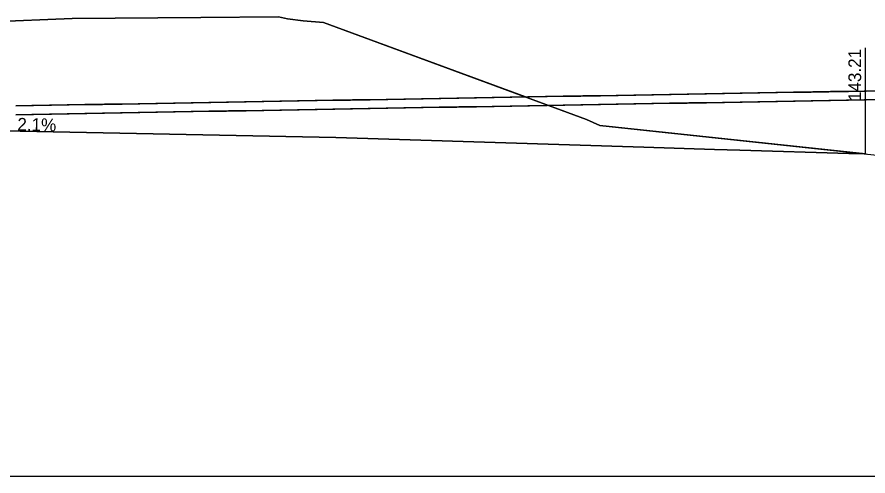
# Model space of a CAD drawing. Extents: x -26 to 4403, y -13 to 9578.
# Drawn here: x 1132.06 to 1180.11, y 1000 to 1025.95 of the extents above; entities that cross this region are included whole.
import ezdxf

# ---------------------------------------------------------------- set-up
doc = ezdxf.new("R2010")
doc.units = 0
for name, color, linetype in [('CONST_LV3', 7, 'Continuous'), ('DTM_CORRIDOR', 7, 'Continuous'), ('DTM_P_FINISHED_GRADE', 7, 'Continuous'), ('DTM_X_GROUND', 7, 'Continuous'), ('SLOPE_STAKES_FILL', 7, 'Continuous'), ('XS_CELL', 7, 'Continuous'), ('XS_M_SHAPES_EARTHWORK', 7, 'Continuous'), ('XS_P_DR_GRAVEL', 7, 'Continuous'), ('XS_P_GROUND', 7, 'Continuous'), ('XS_P_TX_CLEARZONE', 7, 'Continuous'), ('XS_P_TX_FS_BS', 7, 'Continuous')]:
    doc.layers.add(name, color=color, linetype=linetype)

msp = doc.modelspace()

# ---------------------------------------------------------------- linework, layer by layer
at = {"layer": 'CONST_LV3'}
msp.add_lwpolyline([(1132, 1020.927), (1132.897, 1020.942), (1133, 1020.944), (1133.897, 1020.96), (1134, 1020.961), (1134.897, 1020.977), (1135, 1020.979), (1135.897, 1020.995), (1136, 1020.996), (1136.897, 1021.012), (1137, 1021.014), (1137.897, 1021.029), (1138, 1021.031), (1138.897, 1021.047), (1139, 1021.049), (1139.897, 1021.064), (1140, 1021.066), (1140.897, 1021.082), (1141, 1021.083), (1141.897, 1021.099), (1142, 1021.101), (1142.897, 1021.117), (1143, 1021.118), (1143.897, 1021.134), (1144, 1021.136), (1144.897, 1021.151), (1145, 1021.153), (1145.897, 1021.169), (1146, 1021.171), (1146.897, 1021.186), (1147, 1021.188), (1147.897, 1021.204), (1148, 1021.206), (1148.897, 1021.221), (1149, 1021.223), (1149.897, 1021.239), (1150, 1021.24), (1150.897, 1021.256), (1151, 1021.258), (1151.897, 1021.273), (1152, 1021.275), (1152.897, 1021.291), (1153, 1021.293), (1153.897, 1021.308), (1154, 1021.31), (1154.897, 1021.326), (1155, 1021.328), (1155.897, 1021.343), (1156, 1021.345), (1156.897, 1021.361), (1157, 1021.362), (1157.897, 1021.378), (1158, 1021.38), (1158.897, 1021.395), (1159, 1021.397), (1159.897, 1021.413), (1160, 1021.415), (1160.897, 1021.43), (1161, 1021.432), (1161.897, 1021.448), (1162, 1021.45), (1162.897, 1021.465), (1163, 1021.467), (1163.897, 1021.483), (1164, 1021.484), (1164.897, 1021.5), (1165, 1021.502), (1165.897, 1021.518), (1166, 1021.519), (1166.897, 1021.535), (1167, 1021.537), (1167.897, 1021.552), (1168, 1021.554), (1168.897, 1021.57), (1169, 1021.572), (1169.897, 1021.587), (1170, 1021.589), (1170.897, 1021.605), (1171, 1021.606), (1171.897, 1021.622), (1172, 1021.624), (1172.897, 1021.64), (1173, 1021.641), (1173.897, 1021.657), (1174, 1021.659), (1174.897, 1021.674), (1175, 1021.676), (1175.897, 1021.692), (1176, 1021.694), (1176.897, 1021.709), (1177, 1021.711), (1177.897, 1021.727), (1178, 1021.729), (1178.897, 1021.744), (1179, 1021.746), (1179.897, 1021.762), (1180, 1021.763), (1180.897, 1021.779)], dxfattribs=at)
at = {"layer": 'DTM_P_FINISHED_GRADE'}
msp.add_lwpolyline([(1132, 1020.927), (1132.897, 1020.942), (1133, 1020.944), (1133.897, 1020.96), (1134, 1020.961), (1134.897, 1020.977), (1135, 1020.979), (1135.897, 1020.995), (1136, 1020.996), (1136.897, 1021.012), (1137, 1021.014), (1137.897, 1021.029), (1138, 1021.031), (1138.897, 1021.047), (1139, 1021.049), (1139.897, 1021.064), (1140, 1021.066), (1140.897, 1021.082), (1141, 1021.083), (1141.897, 1021.099), (1142, 1021.101), (1142.897, 1021.117), (1143, 1021.118), (1143.897, 1021.134), (1144, 1021.136), (1144.897, 1021.151), (1145, 1021.153), (1145.897, 1021.169), (1146, 1021.171), (1146.897, 1021.186), (1147, 1021.188), (1147.897, 1021.204), (1148, 1021.206), (1148.897, 1021.221), (1149, 1021.223), (1149.897, 1021.239), (1150, 1021.24), (1150.897, 1021.256), (1151, 1021.258), (1151.897, 1021.273), (1152, 1021.275), (1152.897, 1021.291), (1153, 1021.293), (1153.897, 1021.308), (1154, 1021.31), (1154.897, 1021.326), (1155, 1021.328), (1155.897, 1021.343), (1156, 1021.345), (1156.897, 1021.361), (1157, 1021.362), (1157.897, 1021.378), (1158, 1021.38), (1158.897, 1021.395), (1159, 1021.397), (1159.897, 1021.413), (1160, 1021.415), (1160.897, 1021.43), (1161, 1021.432), (1161.897, 1021.448), (1162, 1021.45), (1162.897, 1021.465), (1163, 1021.467), (1163.897, 1021.483), (1164, 1021.484), (1164.897, 1021.5), (1165, 1021.502), (1165.897, 1021.518), (1166, 1021.519), (1166.897, 1021.535), (1167, 1021.537), (1167.897, 1021.552), (1168, 1021.554), (1168.897, 1021.57), (1169, 1021.572), (1169.897, 1021.587), (1170, 1021.589), (1170.897, 1021.605), (1171, 1021.606), (1171.897, 1021.622), (1172, 1021.624), (1172.897, 1021.64), (1173, 1021.641), (1173.897, 1021.657), (1174, 1021.659), (1174.897, 1021.674), (1175, 1021.676), (1175.897, 1021.692), (1176, 1021.694), (1176.897, 1021.709), (1177, 1021.711), (1177.897, 1021.727), (1178, 1021.729), (1178.897, 1021.744), (1179, 1021.746), (1179.897, 1021.762), (1180, 1021.763), (1180.897, 1021.779)], dxfattribs=at)
at = {"layer": 'DTM_X_GROUND'}
msp.add_lwpolyline([(1084.364, 1020.049), (1100.532, 1021.44), (1114.605, 1024.089), (1116.924, 1024.52), (1120.223, 1025.074), (1123.578, 1025.386), (1123.824, 1025.384), (1125.939, 1025.479), (1126.01, 1025.486), (1135.182, 1025.868), (1142.445, 1025.917), (1146.83, 1025.95), (1147.343, 1025.854), (1148.21, 1025.742), (1149.366, 1025.63), (1164.218, 1020.156), (1164.971, 1019.814), (1182.014, 1017.995), (1182.294, 1017.975), (1182.479, 1017.946), (1182.623, 1017.982), (1200.1, 1016.861), (1205.856, 1017.542), (1237.811, 1018.169)], dxfattribs=at)
at = {"layer": 'XS_CELL'}
msp.add_line((1000, 1000), (1250, 1000), dxfattribs=at)
at = {"layer": 'XS_M_SHAPES_EARTHWORK'}
for points in [[(1126.01, 1025.486), (1135.182, 1025.868), (1142.445, 1025.917), (1146.83, 1025.95), (1147.343, 1025.854), (1148.21, 1025.742), (1149.366, 1025.63), (1162.062, 1020.951), (1162, 1020.95), (1161.897, 1020.948), (1161, 1020.932), (1160.897, 1020.93), (1160, 1020.915), (1159.897, 1020.913), (1159, 1020.897), (1158.897, 1020.895), (1158, 1020.88), (1157.897, 1020.878), (1157, 1020.862), (1156.897, 1020.861), (1156, 1020.845), (1155.897, 1020.843), (1155, 1020.828), (1154.897, 1020.826), (1154, 1020.81), (1153.897, 1020.808), (1153, 1020.793), (1152.897, 1020.791), (1152, 1020.775), (1151.897, 1020.773), (1151, 1020.758), (1150.897, 1020.756), (1150, 1020.74), (1149.897, 1020.739), (1149, 1020.723), (1148.897, 1020.721), (1148, 1020.706), (1147.897, 1020.704), (1147, 1020.688), (1146.897, 1020.686), (1146, 1020.671), (1145.897, 1020.669), (1145, 1020.653), (1144.897, 1020.651), (1144, 1020.636), (1143.897, 1020.634), (1143, 1020.618), (1142.897, 1020.617), (1142, 1020.601), (1141.897, 1020.599), (1141, 1020.583), (1140.897, 1020.582), (1140, 1020.566), (1139.897, 1020.564), (1139, 1020.549), (1138.897, 1020.547), (1138, 1020.531), (1137.897, 1020.529), (1137, 1020.514), (1136.897, 1020.512), (1136, 1020.496), (1135.897, 1020.495), (1135, 1020.479), (1134.897, 1020.477), (1134, 1020.461), (1133.897, 1020.46), (1133, 1020.444), (1132.897, 1020.442), (1132, 1020.427)], [(1180.897, 1021.279), (1180, 1021.263), (1179.897, 1021.262), (1179, 1021.246), (1178.897, 1021.244), (1178, 1021.229), (1177.897, 1021.227), (1177, 1021.211), (1176.897, 1021.209), (1176, 1021.194), (1175.897, 1021.192), (1175, 1021.176), (1174.897, 1021.174), (1174, 1021.159), (1173.897, 1021.157), (1173, 1021.141), (1172.897, 1021.14), (1172, 1021.124), (1171.897, 1021.122), (1171, 1021.106), (1170.897, 1021.105), (1170, 1021.089), (1169.897, 1021.087), (1169, 1021.072), (1168.897, 1021.07), (1168, 1021.054), (1167.897, 1021.052), (1167, 1021.037), (1166.897, 1021.035), (1166, 1021.019), (1165.897, 1021.018), (1165, 1021.002), (1164.897, 1021), (1164, 1020.984), (1163.897, 1020.983), (1163, 1020.967), (1162.897, 1020.965), (1162.062, 1020.951), (1164.218, 1020.156), (1164.971, 1019.814), (1182.014, 1017.995)]]:
    msp.add_lwpolyline(points, dxfattribs=at)
at = {"layer": 'XS_P_DR_GRAVEL'}
for points in [[(1180.897, 1021.779), (1180, 1021.763), (1179.897, 1021.762), (1179, 1021.746), (1178.897, 1021.744), (1178, 1021.729), (1177.897, 1021.727), (1177, 1021.711), (1176.897, 1021.709), (1176, 1021.694), (1175.897, 1021.692), (1175, 1021.676), (1174.897, 1021.674), (1174, 1021.659), (1173.897, 1021.657), (1173, 1021.641), (1172.897, 1021.64), (1172, 1021.624), (1171.897, 1021.622), (1171, 1021.606), (1170.897, 1021.605), (1170, 1021.589), (1169.897, 1021.587), (1169, 1021.572), (1168.897, 1021.57), (1168, 1021.554), (1167.897, 1021.552), (1167, 1021.537), (1166.897, 1021.535), (1166, 1021.519), (1165.897, 1021.518), (1165, 1021.502), (1164.897, 1021.5), (1164, 1021.484), (1163.897, 1021.483), (1163, 1021.467), (1162.897, 1021.465), (1162, 1021.45), (1161.897, 1021.448), (1161, 1021.432), (1160.897, 1021.43), (1160, 1021.415), (1159.897, 1021.413), (1159, 1021.397), (1158.897, 1021.395), (1158, 1021.38), (1157.897, 1021.378), (1157, 1021.362), (1156.897, 1021.361), (1156, 1021.345), (1155.897, 1021.343), (1155, 1021.328), (1154.897, 1021.326), (1154, 1021.31), (1153.897, 1021.308), (1153, 1021.293), (1152.897, 1021.291), (1152, 1021.275), (1151.897, 1021.273), (1151, 1021.258), (1150.897, 1021.256), (1150, 1021.24), (1149.897, 1021.239), (1149, 1021.223), (1148.897, 1021.221), (1148, 1021.206), (1147.897, 1021.204), (1147, 1021.188), (1146.897, 1021.186), (1146, 1021.171), (1145.897, 1021.169), (1145, 1021.153), (1144.897, 1021.151), (1144, 1021.136), (1143.897, 1021.134), (1143, 1021.118), (1142.897, 1021.117), (1142, 1021.101), (1141.897, 1021.099), (1141, 1021.083), (1140.897, 1021.082), (1140, 1021.066), (1139.897, 1021.064), (1139, 1021.049), (1138.897, 1021.047), (1138, 1021.031), (1137.897, 1021.029), (1137, 1021.014), (1136.897, 1021.012), (1136, 1020.996), (1135.897, 1020.995), (1135, 1020.979), (1134.897, 1020.977), (1134, 1020.961), (1133.897, 1020.96), (1133, 1020.944), (1132.897, 1020.942), (1132, 1020.927)], [(1132, 1020.427), (1132.897, 1020.442), (1133, 1020.444), (1133.897, 1020.46), (1134, 1020.461), (1134.897, 1020.477), (1135, 1020.479), (1135.897, 1020.495), (1136, 1020.496), (1136.897, 1020.512), (1137, 1020.514), (1137.897, 1020.529), (1138, 1020.531), (1138.897, 1020.547), (1139, 1020.549), (1139.897, 1020.564), (1140, 1020.566), (1140.897, 1020.582), (1141, 1020.583), (1141.897, 1020.599), (1142, 1020.601), (1142.897, 1020.617), (1143, 1020.618), (1143.897, 1020.634), (1144, 1020.636), (1144.897, 1020.651), (1145, 1020.653), (1145.897, 1020.669), (1146, 1020.671), (1146.897, 1020.686), (1147, 1020.688), (1147.897, 1020.704), (1148, 1020.706), (1148.897, 1020.721), (1149, 1020.723), (1149.897, 1020.739), (1150, 1020.74), (1150.897, 1020.756), (1151, 1020.758), (1151.897, 1020.773), (1152, 1020.775), (1152.897, 1020.791), (1153, 1020.793), (1153.897, 1020.808), (1154, 1020.81), (1154.897, 1020.826), (1155, 1020.828), (1155.897, 1020.843), (1156, 1020.845), (1156.897, 1020.861), (1157, 1020.862), (1157.897, 1020.878), (1158, 1020.88), (1158.897, 1020.895), (1159, 1020.897), (1159.897, 1020.913), (1160, 1020.915), (1160.897, 1020.93), (1161, 1020.932), (1161.897, 1020.948), (1162, 1020.95), (1162.897, 1020.965), (1163, 1020.967), (1163.897, 1020.983), (1164, 1020.984), (1164.897, 1021), (1165, 1021.002), (1165.897, 1021.018), (1166, 1021.019), (1166.897, 1021.035), (1167, 1021.037), (1167.897, 1021.052), (1168, 1021.054), (1168.897, 1021.07), (1169, 1021.072), (1169.897, 1021.087), (1170, 1021.089), (1170.897, 1021.105), (1171, 1021.106), (1171.897, 1021.122), (1172, 1021.124), (1172.897, 1021.14), (1173, 1021.141), (1173.897, 1021.157), (1174, 1021.159), (1174.897, 1021.174), (1175, 1021.176), (1175.897, 1021.192), (1176, 1021.194), (1176.897, 1021.209), (1177, 1021.211), (1177.897, 1021.227), (1178, 1021.229), (1178.897, 1021.244), (1179, 1021.246), (1179.897, 1021.262), (1180, 1021.263), (1180.897, 1021.279)]]:
    msp.add_lwpolyline(points, dxfattribs=at)
at = {"layer": 'XS_P_GROUND'}
for p, q in [((1149.366, 1025.63), (1148.21, 1025.742)), ((1160.767, 1021.428), (1149.366, 1025.63)), ((1135, 1020.979), (1135.897, 1020.995)), ((1138.897, 1021.047), (1139, 1021.049)), ((1140.897, 1021.082), (1141, 1021.083)), ((1141, 1021.083), (1141.897, 1021.099)), ((1141.897, 1021.099), (1142, 1021.101)), ((1142, 1021.101), (1142.897, 1021.117)), ((1148, 1021.206), (1148.897, 1021.221)), ((1148.897, 1021.221), (1149, 1021.223)), ((1152, 1021.275), (1152.897, 1021.291)), ((1153.897, 1021.308), (1154, 1021.31)), ((1154, 1021.31), (1154.897, 1021.326)), ((1154.897, 1021.326), (1155, 1021.328)), ((1158.897, 1021.395), (1159, 1021.397)), ((1159, 1021.397), (1159.897, 1021.413)), ((1179.962, 1018.214), (1164.971, 1019.814))]:
    msp.add_line(p, q, dxfattribs=at)
for points in [[(1164.971, 1019.814), (1164.218, 1020.156), (1149.366, 1025.63), (1148.21, 1025.742), (1147.343, 1025.854), (1146.83, 1025.95), (1142.445, 1025.917), (1135.182, 1025.868), (1126.01, 1025.486), (1125.939, 1025.479), (1123.824, 1025.384), (1123.578, 1025.386), (1120.223, 1025.074), (1116.924, 1024.52), (1114.605, 1024.089), (1100.532, 1021.44), (1086.141, 1020.202)], [(1135.182, 1025.868), (1126.01, 1025.486), (1125.939, 1025.479), (1123.824, 1025.384), (1123.578, 1025.386)], [(1148.21, 1025.742), (1147.343, 1025.854), (1146.83, 1025.95), (1142.445, 1025.917), (1135.182, 1025.868)], [(1135.897, 1020.995), (1136, 1020.996), (1136.897, 1021.012)], [(1136.897, 1021.012), (1137, 1021.014), (1137.897, 1021.029), (1138, 1021.031), (1138.897, 1021.047)], [(1139, 1021.049), (1139.897, 1021.064), (1140, 1021.066), (1140.897, 1021.082)], [(1142.897, 1021.117), (1143, 1021.118), (1143.897, 1021.134)], [(1143.897, 1021.134), (1144, 1021.136), (1144.897, 1021.151), (1145, 1021.153)], [(1145, 1021.153), (1145.897, 1021.169), (1146, 1021.171)], [(1146, 1021.171), (1146.897, 1021.186), (1147, 1021.188)], [(1147, 1021.188), (1147.897, 1021.204), (1148, 1021.206)], [(1149, 1021.223), (1149.897, 1021.239), (1150, 1021.24), (1150.897, 1021.256), (1151, 1021.258), (1151.897, 1021.273), (1152, 1021.275)], [(1152.897, 1021.291), (1153, 1021.293), (1153.897, 1021.308)], [(1155, 1021.328), (1155.897, 1021.343), (1156, 1021.345)], [(1156, 1021.345), (1156.897, 1021.361), (1157, 1021.362)], [(1157, 1021.362), (1157.897, 1021.378), (1158, 1021.38), (1158.897, 1021.395)], [(1159.897, 1021.413), (1160, 1021.415), (1160.767, 1021.428)], [(1132, 1020.927), (1132.897, 1020.942), (1133, 1020.944)], [(1133, 1020.944), (1133.897, 1020.96), (1134, 1020.961)], [(1134, 1020.961), (1134.897, 1020.977), (1135, 1020.979)], [(1179.962, 1018.214), (1179.027, 1018.229), (1172.878, 1018.416), (1171.441, 1018.462), (1167.448, 1018.585), (1150.067, 1019.142), (1130.346, 1019.54), (1123.445, 1019.698), (1121.832, 1019.725), (1121.672, 1019.729), (1117.182, 1019.804), (1093.824, 1020.123), (1088.787, 1020.175), (1088.318, 1020.181), (1086.141, 1020.202)], [(1086.141, 1020.202), (1088.318, 1020.181), (1088.787, 1020.175), (1093.824, 1020.123), (1117.182, 1019.804), (1121.672, 1019.729), (1121.832, 1019.725), (1123.445, 1019.698), (1130.346, 1019.54), (1150.067, 1019.142), (1167.448, 1018.585), (1171.441, 1018.462), (1172.878, 1018.416), (1179.027, 1018.229), (1179.962, 1018.214)]]:
    msp.add_lwpolyline(points, dxfattribs=at)
at = {"layer": 'XS_P_TX_CLEARZONE'}
msp.add_line((1179.962, 1018.214), (1179.962, 1024.214), dxfattribs=at)
msp.add_line((1179.962, 1018.214), (1179.962, 1024.214), dxfattribs=at)
msp.add_line((1179.962, 1018.214), (1179.962, 1024.214), dxfattribs=at)
msp.add_line((1179.962, 1018.214), (1179.962, 1024.214), dxfattribs=at)
msp.add_line((1179.962, 1018.214), (1179.962, 1024.214), dxfattribs=at)
msp.add_line((1179.962, 1018.214), (1179.962, 1024.214), dxfattribs=at)

# ---------------------------------------------------------------- texts
at = {"layer": 'DTM_CORRIDOR'}
msp.add_text('X', height=0.12, dxfattribs=at).set_placement((1179.923, 1018.154))
at = {"layer": 'SLOPE_STAKES_FILL'}
msp.add_text('X', height=0.12, dxfattribs=at).set_placement((1179.923, 1018.154))
at = {"layer": 'XS_P_TX_CLEARZONE'}
msp.add_text('143.21', height=0.72, rotation=90, dxfattribs=at).set_placement((1179.722, 1021.2))
msp.add_text('143.21', height=0.72, rotation=90, dxfattribs=at).set_placement((1179.722, 1021.2))
msp.add_text('143.21', height=0.72, rotation=90, dxfattribs=at).set_placement((1179.722, 1021.2))
msp.add_text('143.21', height=0.72, rotation=90, dxfattribs=at).set_placement((1179.722, 1021.2))
msp.add_text('143.21', height=0.72, rotation=90, dxfattribs=at).set_placement((1179.722, 1021.2))
msp.add_text('143.21', height=0.72, rotation=90, dxfattribs=at).set_placement((1179.722, 1021.2))
at = {"layer": 'XS_P_TX_FS_BS'}
msp.add_text('2.1%', height=0.72, rotation=358.7862, dxfattribs=at).set_placement((1132.075, 1019.529))
msp.add_text('2.1%', height=0.72, rotation=358.7862, dxfattribs=at).set_placement((1132.075, 1019.529))
msp.add_text('2.1%', height=0.72, rotation=358.7862, dxfattribs=at).set_placement((1132.075, 1019.529))

doc.saveas('drawing.dxf')
